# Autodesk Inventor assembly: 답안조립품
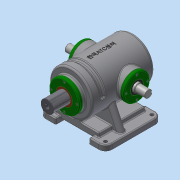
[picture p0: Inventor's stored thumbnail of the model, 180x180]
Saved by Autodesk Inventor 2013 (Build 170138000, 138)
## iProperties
Created: 2018-06
Part Number: 답안조립품
Document SubType Name: Assembly
Designer: Administrator
Mass: 8560.47 g
Surface Area: 4294.68 cm^2
Volume: 2307.06 cm^3
Density: 3.71055 g/cm^3
Author: Administrator
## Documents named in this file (13)
- C:\Users\Administrator\Desktop\380628V1008\답안조립품.iam
- C:\Users\Administrator\Desktop\380628V1008\본체.ipt
- C:\Users\Administrator\Desktop\380628V1008\가변스프링.ipt
- C:\Users\Administrator\Desktop\380628V1008\베어링 6205.ipt
- 베어링 6205.ipt
- C:\Users\Administrator\Desktop\380628V1008\볼트 M4.ipt
- C:\Users\Administrator\Desktop\380628V1008\부시.ipt
- C:\Users\Administrator\Desktop\380628V1008\슬라이드 커버.ipt
- C:\Users\Administrator\Desktop\380628V1008\슬라이드.ipt
- C:\Users\Administrator\Desktop\380628V1008\오일실.ipt
- 오일실.ipt
- C:\Users\Administrator\Desktop\380628V1008\축 커버.ipt
- C:\Users\Administrator\Desktop\380628V1008\편심축.ipt
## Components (1 placed, 1 different names)
1. 가변스프링:1
